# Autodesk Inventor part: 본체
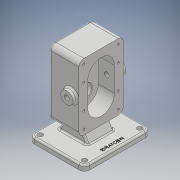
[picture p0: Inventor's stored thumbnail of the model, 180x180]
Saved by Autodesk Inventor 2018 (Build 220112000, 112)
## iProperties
Created: 2020-04
Part Number: 본체
Material: 일반
Document SubType Name: Modeling
Designer: USER
Density: 1 g/cm^3
Appearance: 기본값
Author: USER
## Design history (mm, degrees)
sketch "스케치1"
  geometry: L1 (0, 0)-(80, 0); L2 (80, 0)-(80, 120); L3 (80, 120)-(0, 120); L4 (0, 120)-(0, 0)
  constraints: 8 end point, 2 parallel, 1 horizontal, 1 perpendicular
  dimensions: "d0" = 80 distance of L2.end L3.end; "d1" = 120 distance of L3.end L1.start
extrude "돌출1" new body sketch "스케치1" distance "d2" = 53; taper "d3" = 0 deg
node "작업 평면1"
sketch "스케치3"
  geometry: L1 (-82, 40)-(-38, 40); L2 (-82, 16)-(-38, 16); L3 (-38, 64)-(-82, 64); L4 (-120, 80)-(-120, 0) reference; L5 (-120, 0)-(0, 0) reference; A1 r 24 centre (-82, 40) between (-82, 64) and (-82, 16); A2 r 24 centre (-38, 40) between (-38, 16) and (-38, 64); 4 further points
  constraints: 8 end point, 5 point on circle, 4 tangent, 3 midpoint, 2 centre point, 1 horizontal, 1 horizontal alignment, 1 parallel, 1 vertical alignment
  dimensions: "d9" = 24 radius of A1; "d10" = 22 distance of L1.start point (-60, 40)
extrude "돌출3" cut sketch "스케치3" distance "d11" = 29; taper "d12" = 0 deg
sketch "스케치4"
  geometry: C1 r 12.5 at (-82, 40); C2 r 12.5 at (-38, 40); A1 r 24 centre (-82, 40) between (-82, 64) and (-82, 16) reference; A2 r 24 centre (-38, 40) between (-38, 16) and (-38, 64) reference; 1 further point
  constraints: 2 centre point, 2 concentric
  dimensions: "d13" = 25 diameter of C1; "d14" = 25 diameter of C2
extrude "돌출4" cut sketch "스케치4" distance "d15" = 15; taper "d16" = 0 deg
sketch "스케치5"
  geometry: C1 r 19 at (82, 40); C2 r 12.5 at (82, 40) reference; A1 r 24 centre (82, 40) between (82, 16) and (82, 64) reference; 1 further point
  constraints: 2 concentric, 1 centre point
  dimensions: "d17" = 38 diameter of C1
extrude "돌출5" join sketch "스케치5" distance "d18" = 17; taper "d19" = 0 deg
sketch "스케치6"
  geometry: C1 r 14 at (0, 0); C2 r 19 at (0, 0) reference; 1 further point
  constraints: 1 centre point, 1 concentric
  dimensions: "d20" = 28 diameter of C1
extrude "돌출6" cut sketch "스케치6" distance "d21" = 7.3; taper "d22" = 0 deg
sketch "스케치7"
  geometry: C1 r 8.5 at (0, 0); C2 r 14 at (0, 0) reference; 1 further point
  constraints: 1 centre point, 1 coincident
  dimensions: "d23" = 17 diameter of C1
extrude "돌출7" cut sketch "스케치7" extent not by distance; stored distance "d24" = 7.3; taper "d25" = 0 deg
sketch "스케치8"
  geometry: L1 (0, 0)-(53, 0) reference; L2 (53, 120)-(53, 0) reference; C1 r 11 at (39, 60); 2 further points
  constraints: 1 centre point, 1 horizontal alignment, 1 midpoint
  dimensions: "d26" = 22 diameter of C1; "d29" = 14 distance from line of L2 C1.centre
extrude "돌출8" join sketch "스케치8" distance "d27" = 8; taper "d28" = 0 deg
sketch "스케치9"
  geometry: C1 r 11 at (0, 0) reference; 2 further points
  constraints: 1 coincident
hole "구멍1" sketch "스케치9" at (0, 0) diameter "d30" = 8.917; stored, may be unused: countersink angle "d34" = 90 deg, drill point angle "d36" = 118 deg; dims "d31" = 20, "d32" = 4, "d33" = 2, "d35" = 25.1
node "작업 평면2"
node "작업 평면3"
sketch "스케치12"
  geometry: L1 (0, 80)-(-120, 80) reference; C1 r 8.5 at (-82, 40) reference; C2 r 12.5 at (-38, 40) reference; 9 further points
  constraints: 6 horizontal alignment, 6 vertical alignment
  dimensions: "d43" = 102 distance of point (-9, 71) point (-111, 71); "d44" = 29 distance of point (-82, 71) point (-111, 71); "d45" = 62 distance of point (-111, 9) point (-111, 71); "d46" = 9 distance from line of point (-111, 71) L1
hole "구멍2" sketch "스케치12" at (-111, 9), (-82, 9), (-38, 9), (-9, 9), (-9, 71), (-38, 71), (-82, 71), (-111, 71) diameter "d47" = 4.134; stored, may be unused: countersink angle "d51" = 90 deg, drill point angle "d53" = 118 deg; dims "d48" = 10, "d49" = 4, "d50" = 2, "d52" = 12
fillet "모깎기1" dims "d65" = 9
node "작업 평면4"
sketch "스케치14"
  geometry: L1 (-17, 50)-(-17, 12) reference; L2 (-17, 91)-(83, 91); L3 (83, 91)-(83, -29); L4 (83, -29)-(-17, -29); L5 (-17, -29)-(-17, 91); L6 (53, 0)-(53, 62) reference; 3 further points
  constraints: 8 end point, 2 midpoint, 2 parallel, 1 horizontal, 1 horizontal alignment, 1 perpendicular, 1 point on line
  dimensions: "d69" = 100 distance of L2.start L2.end; "d70" = 120 distance of L2.end L3.end
extrude "돌출10" join sketch "스케치14" distance "d71" = 10; taper "d72" = 0 deg
node "작업 평면5"
sketch "스케치15"
  geometry: L1 (70, -10)-(53.698, -38.236); L2 (0, -10)-(100, -10) reference; L3 (17, -10)-(33.302, -38.236); L4 (0, 0)-(0, -10) reference; L5 (70, -10)-(17, -10); L6 (33.302, -38.236)-(53.698, -38.236); L7 (70, -39)-(17, -39) reference; 1 further point
  constraints: 8 end point, 2 point on line, 1 horizontal, 1 parallel
  dimensions: "d73" = 17 distance from line of L4 L3.start; "d74" = 53 distance of L3.start L1.start; "d75" = 60 deg angle of L2 L3; "d76" = 60 deg angle of L2 L1
extrude "돌출11" join sketch "스케치15" stored distance "d77" = 48; taper "d78" = 0 deg
sketch "스케치16"
  geometry: L1 (83, -29)-(83, 91) reference; L2 (-17, -29)-(83, -29) reference; L3 (-17, 91)-(-17, -29) reference; L4 (83, 91)-(-17, 91) reference; 5 further points
  constraints: 2 horizontal alignment, 2 vertical alignment
  dimensions: "d79" = 10 distance from line of L1 point (73, -19); "d80" = 10 distance from line of L2 point (73, -19); "d81" = 10 distance from line of L3 point (-7, -19); "d82" = 10 distance from line of L4 point (-7, 81)
hole "구멍4" sketch "스케치16" at (73, -19), (-7, -19), (-7, 81), (73, 81) diameter "d83" = 9; stored, may be unused: countersink angle "d87" = 90 deg, drill point angle "d89" = 118 deg; dims "d84" = 10, "d85" = 4, "d86" = 2, "d88" = 12
fillet "모깎기2" dims "d90" = 10
fillet "모깎기3" dims "d91" = 3
fillet "모깎기4" dims "d92" = 3
fillet "모깎기5" dims "d93" = 3
chamfer "모따기1" distance "d94" = 0.7; stored, may be unused: second distance "d95" = 2, angle "d96" = 30 deg
chamfer "모따기2" distance "d97" = 1; stored, may be unused: second distance "d98" = 2, angle "d99" = 45 deg
chamfer "모따기3" distance "d100" = 1; stored, may be unused: second distance "d101" = 2, angle "d102" = 45 deg
fillet "모깎기6" dims "d103" = 3
sketch "스케치17"
  geometry: L1 (-7, -29)-(73, -29) reference; L2 (83, -19)-(83, 81) reference; 2 further points
  constraints: 1 other
  dimensions: "d104" = 60 distance from line of L1 point (73, 31); "d105" = 10 distance from line of L2 point (73, 31)
feature "엠보싱1" sketch "스케치17" dims "d0" = 80, "d1" = 120, "d106" = 0.5, "d107" = 0
fillet "모깎기9" dims "d110" = 0.5
node "솔리드1"
mirror "미러1"
node "투영된 루프1"
